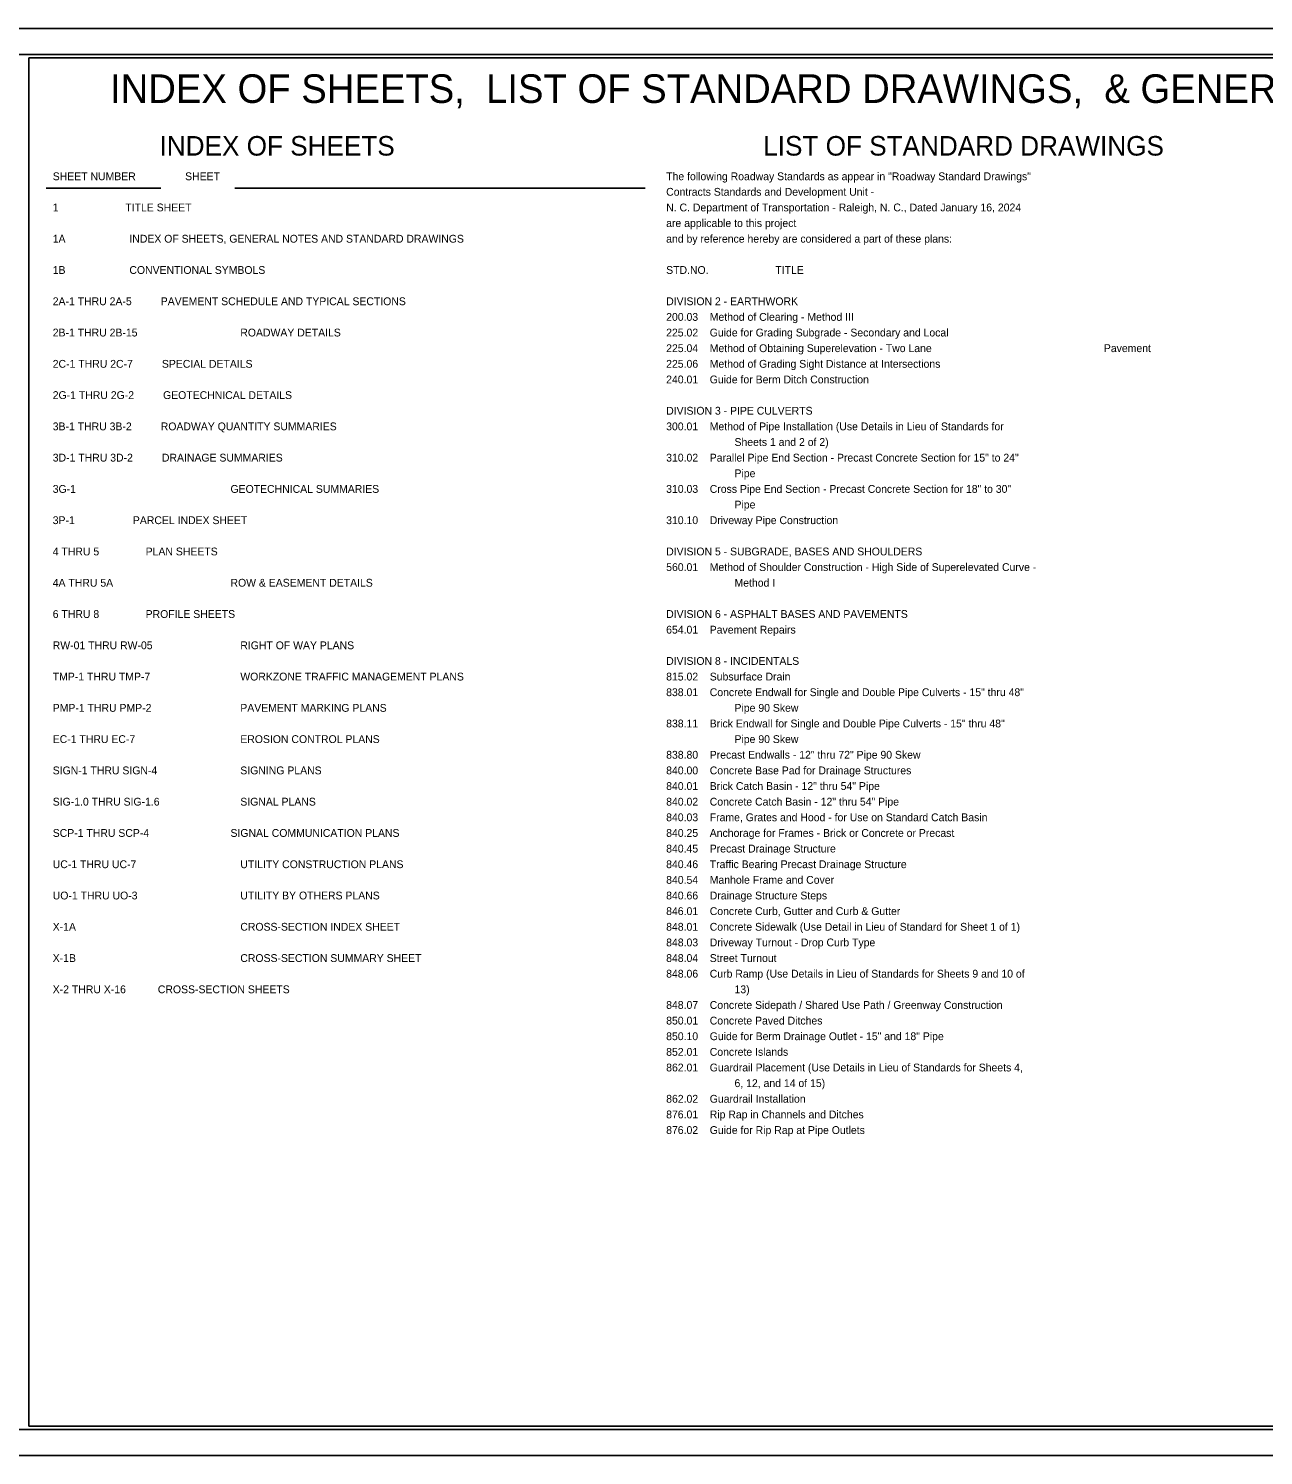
# Model space of a CAD drawing. Extents: x -1492 to 2447, y -56 to 1953.
# Drawn here: x 0 to 948, y -22 to 1072 of the extents above; entities that cross this region are included whole.
import ezdxf

# ---------------------------------------------------------------- set-up
doc = ezdxf.new("R2010")
doc.units = 0
for name, color, linetype in [('Scratch_Level_3', 7, 'Continuous'), ('Sheet Cutting Line CELL', 7, 'Continuous'), ('Sheet Data Field CELL', 7, 'Continuous'), ('Sheet Data Text CELL', 7, 'Continuous'), ('Sheet Plan CELL', 7, 'Continuous'), ('Sheet Plot Border Inside CELL', 7, 'Continuous'), ('Sheet Plot Border Outside CELL', 7, 'Continuous'), ('Sheet Summary CELL', 7, 'Continuous')]:
    doc.layers.add(name, color=color, linetype=linetype)

msp = doc.modelspace()

# ---------------------------------------------------------------- linework, layer by layer
at = {"layer": 'Scratch_Level_3'}
for p, q in [((0, 1050), (500, 1050)), ((500, 1050), (1000, 1050))]:
    msp.add_line(p, q, dxfattribs=at)
at = {"layer": 'Sheet Cutting Line CELL'}
for p, q in [((1517, 1072.5), (-166.5, 1072.5)), ((-166.5, -22.5), (1517, -22.5))]:
    msp.add_line(p, q, dxfattribs=at)
at = {"layer": 'Sheet Data Text CELL'}
for p, q in [((13.3, 950), (101.4, 950)), ((158, 950), (473.1, 950))]:
    msp.add_line(p, q, dxfattribs=at)
at = {"layer": 'Sheet Plan CELL'}
for p, q in [((0, 1050), (0, 1050)), ((0, 0), (0, 0))]:
    msp.add_line(p, q, dxfattribs=at)
msp.add_lwpolyline([(1500, 1050), (0, 1050), (0, 0), (1500, 0)], close=True, dxfattribs=at)
at = {"layer": 'Sheet Plot Border Inside CELL'}
msp.add_lwpolyline([(-153.5, -2.5), (1512.5, -2.5), (1512.5, 1052.5), (-153.5, 1052.5)], close=True, dxfattribs=at)
at = {"layer": 'Sheet Plot Border Outside CELL'}
msp.add_lwpolyline([(-166.5, -22.5), (1517, -22.5), (1517, 1072.5), (-166.5, 1072.5)], close=True, dxfattribs=at)

# ---------------------------------------------------------------- texts
at = {"layer": 'Sheet Data Field CELL'}
for s, p in [('INDEX OF SHEETS', (100.3, 975)), ('LIST OF STANDARD DRAWINGS', (563.7, 975))]:
    msp.add_text(s, height=15, dxfattribs=at).set_placement(p)
at = {"layer": 'Sheet Data Text CELL'}
for s, p in [('SHEET NUMBER                 SHEET   ', (18.3, 956.1)), ('The following Roadway Standards as appear in "Roadway Standard Drawings" ', (489.2, 956.1)), ('Contracts Standards and Development Unit -', (489.2, 944.2)), ('1                       TITLE SHEET', (18.3, 932.2)), ('N. C. Department of Transportation - Raleigh, N. C., Dated January 16, 2024 ', (489.2, 932.2)), ('are applicable to this project', (489.2, 920.2)), ('1A                      INDEX OF SHEETS, GENERAL NOTES AND STANDARD DRAWINGS', (18.3, 908.2)), ('and by reference hereby are considered a part of these plans:', (489.2, 908.2)), ('1B                      CONVENTIONAL SYMBOLS', (18.3, 884.2)), ('STD.NO.                       TITLE', (489.2, 884.2)), ('2A-1 THRU 2A-5          PAVEMENT SCHEDULE AND TYPICAL SECTIONS', (18.3, 860.2)), ('DIVISION 2 - EARTHWORK', (489.2, 860.2)), ('200.03    Method of Clearing - Method III', (489.2, 848.2)), ('2B-1 THRU 2B-15         ', (18.3, 836.2)), ('ROADWAY DETAILS', (162.3, 836.2)), ('225.02    Guide for Grading Subgrade - Secondary and Local', (489.2, 836.2)), ('225.04    Method of Obtaining Superelevation - Two Lane ', (489.2, 824.2)), ('Pavement', (825.2, 824.2)), ('2C-1 THRU 2C-7          SPECIAL DETAILS', (18.3, 812.2)), ('225.06    Method of Grading Sight Distance at Intersections', (489.2, 812.2)), ('240.01    Guide for Berm Ditch Construction', (489.2, 800.2)), ('2G-1 THRU 2G-2          GEOTECHNICAL DETAILS', (18.3, 788.2)), ('DIVISION 3 - PIPE CULVERTS', (489.2, 776.2)), ('3B-1 THRU 3B-2          ROADWAY QUANTITY SUMMARIES', (18.3, 764.2)), ('300.01    Method of Pipe Installation (Use Details in Lieu of Standards for ', (489.2, 764.2)), ('  Sheets 1 and 2 of 2)', (537.2, 752.2)), ('3D-1 THRU 3D-2          DRAINAGE SUMMARIES', (18.3, 740.2)), ('310.02    Parallel Pipe End Section - Precast Concrete Section for 15" to 24" ', (489.2, 740.2)), ('  Pipe', (537.2, 728.2)), ('3G-1', (18.3, 716.2)), ('  GEOTECHNICAL SUMMARIES', (150.3, 716.2)), ('310.03    Cross Pipe End Section - Precast Concrete Section for 18" to 30"', (489.2, 716.2)), ('  Pipe', (537.2, 704.2)), ('3P-1                    PARCEL INDEX SHEET', (18.3, 692.2)), ('310.10    Driveway Pipe Construction', (489.2, 692.2)), ('4 THRU 5                PLAN SHEETS', (18.3, 668.2)), ('DIVISION 5 - SUBGRADE, BASES AND SHOULDERS', (489.2, 668.2)), ('560.01    Method of Shoulder Construction - High Side of Superelevated Curve - ', (489.2, 656.2)), ('4A THRU 5A', (18.3, 644.2)), ('  ROW & EASEMENT DETAILS', (150.3, 644.2)), ('  Method I', (537.2, 644.2)), ('6 THRU 8                PROFILE SHEETS', (18.3, 620.2)), ('DIVISION 6 - ASPHALT BASES AND PAVEMENTS', (489.2, 620.2)), ('654.01    Pavement Repairs', (489.2, 608.2)), ('RW-01 THRU RW-05', (18.3, 596.2)), ('RIGHT OF WAY PLANS', (162.3, 596.2)), ('DIVISION 8 - INCIDENTALS', (489.2, 584.2)), ('TMP-1 THRU TMP-7', (18.3, 572.2)), ('WORKZONE TRAFFIC MANAGEMENT PLANS', (162.3, 572.2)), ('815.02    Subsurface Drain', (489.2, 572.2)), ('838.01    Concrete Endwall for Single and Double Pipe Culverts - 15" thru 48"', (489.2, 560.2)), ('PMP-1 THRU PMP-2', (18.3, 548.2)), ('PAVEMENT MARKING PLANS', (162.3, 548.2)), ('  Pipe 90 Skew', (537.2, 548.2)), ('838.11    Brick Endwall for Single and Double Pipe Culverts - 15" thru 48" ', (489.2, 536.2)), ('EC-1 THRU EC-7', (18.3, 524.2)), ('EROSION CONTROL PLANS', (162.3, 524.2)), ('  Pipe 90 Skew', (537.2, 524.2)), ('838.80    Precast Endwalls - 12" thru 72" Pipe 90 Skew', (489.2, 512.2)), ('SIGN-1 THRU SIGN-4', (18.3, 500.2)), ('SIGNING PLANS', (162.3, 500.2)), ('840.00    Concrete Base Pad for Drainage Structures', (489.2, 500.2)), ('840.01    Brick Catch Basin - 12" thru 54" Pipe', (489.2, 488.2)), ('SIG-1.0 THRU SIG-1.6', (18.3, 476.2)), ('SIGNAL PLANS ', (162.3, 476.2)), ('840.02    Concrete Catch Basin - 12" thru 54" Pipe', (489.2, 476.2)), ('840.03    Frame, Grates and Hood - for Use on Standard Catch Basin', (489.2, 464.2)), ('SCP-1 THRU SCP-4', (18.3, 452.2)), ('  SIGNAL COMMUNICATION PLANS', (150.3, 452.2)), ('840.25    Anchorage for Frames - Brick or Concrete or Precast', (489.2, 452.2)), ('840.45    Precast Drainage Structure', (489.2, 440.2)), ('UC-1 THRU UC-7  ', (18.3, 428.2)), ('UTILITY CONSTRUCTION PLANS', (162.3, 428.2)), ('840.46    Traffic Bearing Precast Drainage Structure', (489.2, 428.2)), ('840.54    Manhole Frame and Cover', (489.2, 416.2)), ('UO-1 THRU UO-3', (18.3, 404.2)), ('UTILITY BY OTHERS PLANS', (162.3, 404.2)), ('840.66    Drainage Structure Steps', (489.2, 404.2)), ('846.01    Concrete Curb, Gutter and Curb & Gutter', (489.2, 392.2)), ('X-1A ', (18.3, 380.2)), ('CROSS-SECTION INDEX SHEET', (162.3, 380.2)), ('848.01    Concrete Sidewalk (Use Detail in Lieu of Standard for Sheet 1 of 1)', (489.2, 380.2)), ('848.03    Driveway Turnout - Drop Curb Type', (489.2, 368.2)), ('X-1B', (18.3, 356.2)), ('CROSS-SECTION SUMMARY SHEET', (162.3, 356.2)), ('848.04    Street Turnout', (489.2, 356.2)), ('848.06    Curb Ramp (Use Details in Lieu of Standards for Sheets 9 and 10 of ', (489.2, 344.2)), ('X-2 THRU X-16           CROSS-SECTION SHEETS ', (18.3, 332.2)), ('  13)', (537.2, 332.2)), ('848.07    Concrete Sidepath / Shared Use Path / Greenway Construction', (489.2, 320.2)), ('850.01    Concrete Paved Ditches', (489.2, 308.2)), ('850.10    Guide for Berm Drainage Outlet - 15" and 18" Pipe', (489.2, 296.2)), ('852.01    Concrete Islands', (489.2, 284.2)), ('862.01    Guardrail Placement (Use Details in Lieu of Standards for Sheets 4, ', (489.2, 272.2)), ('  6, 12, and 14 of 15)', (537.2, 260.2)), ('862.02    Guardrail Installation', (489.2, 248.2)), ('876.01    Rip Rap in Channels and Ditches', (489.2, 236.2)), ('876.02    Guide for Rip Rap at Pipe Outlets', (489.2, 224.2))]:
    msp.add_text(s, height=6, dxfattribs=at).set_placement(p)
at = {"layer": 'Sheet Summary CELL'}
msp.add_text('INDEX OF SHEETS,  LIST OF STANDARD DRAWINGS,  & GENERAL NOTES', height=21.95, dxfattribs=at).set_placement((62.3, 1015.4))

doc.saveas('drawing.dxf')
